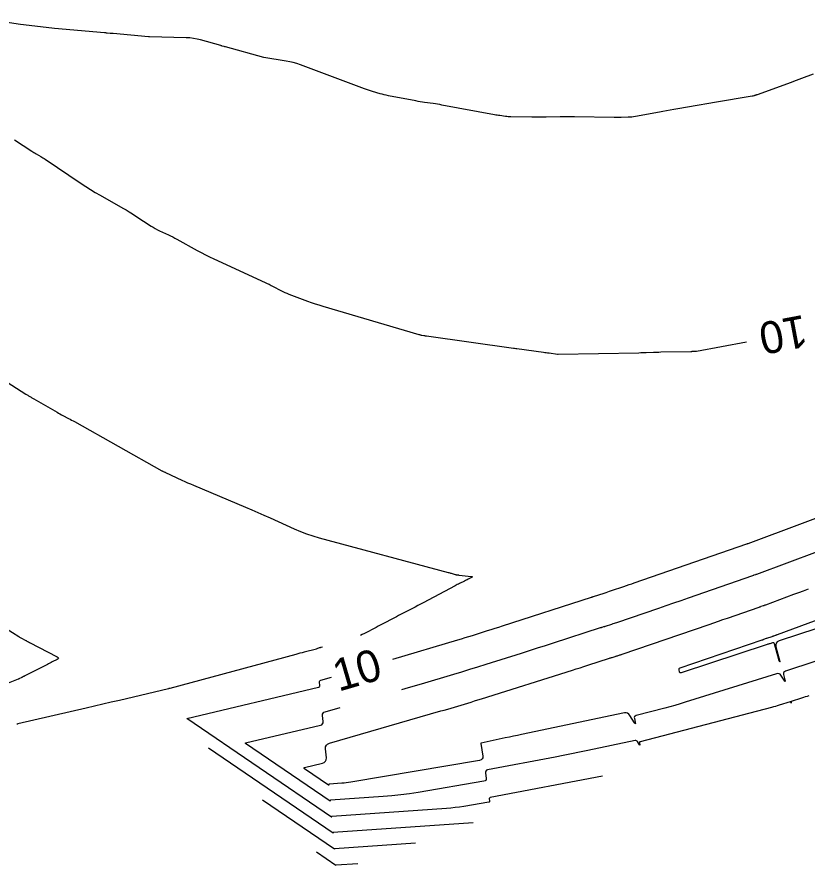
# Model space of a CAD drawing. Extents: x 1797419 to 1809236, y 248759 to 251512.
# Drawn here: x 1797965.5 to 1798113.5, y 248838.1 to 248997 of the extents above; entities that cross this region are included whole.
import ezdxf

# ---------------------------------------------------------------- set-up
doc = ezdxf.new("R2010")
doc.units = 0
doc.layers.add('33', color=7, linetype='Continuous')
doc.layers.add('34', color=7, linetype='Continuous')

msp = doc.modelspace()

# ---------------------------------------------------------------- linework, layer by layer
at = {"layer": '33'}
for points in [[(1797964.99, 248973.98), (1797968.24, 248971.9), (1797968.44, 248971.77), (1797968.65, 248971.64), (1797968.86, 248971.51), (1797969.07, 248971.39), (1797969.92, 248970.9), (1797970.13, 248970.77), (1797970.33, 248970.65), (1797970.54, 248970.51), (1797970.74, 248970.38), (1797977.48, 248965.84), (1797978.36, 248965.26), (1797979.25, 248964.7), (1797980.15, 248964.15), (1797981.06, 248963.63), (1797985.29, 248961.22), (1797985.92, 248960.86), (1797986.53, 248960.48), (1797987.15, 248960.1), (1797987.75, 248959.71), (1797990.61, 248957.84), (1797990.99, 248957.6), (1797991.39, 248957.37), (1797991.79, 248957.16), (1797992.2, 248956.96), (1797993.84, 248956.19), (1797994.25, 248955.99), (1797994.66, 248955.79), (1797995.06, 248955.58), (1797995.46, 248955.36), (1797999.24, 248953.28), (1798000, 248952.87), (1798000.78, 248952.47), (1798001.55, 248952.08), (1798002.34, 248951.71), (1798012, 248947.27), (1798012.37, 248947.1), (1798012.74, 248946.92), (1798013.11, 248946.73), (1798013.47, 248946.54), (1798014.93, 248945.76), (1798015.29, 248945.57), (1798015.67, 248945.4), (1798016.04, 248945.24), (1798016.43, 248945.09), (1798019.9, 248943.79), (1798020.61, 248943.53), (1798021.33, 248943.29), (1798022.05, 248943.05), (1798022.77, 248942.83), (1798040.78, 248937.53), (1798040.89, 248937.5), (1798041.01, 248937.47), (1798041.13, 248937.44), (1798041.25, 248937.41), (1798041.72, 248937.32), (1798041.84, 248937.3), (1798041.96, 248937.28), (1798042.08, 248937.26), (1798042.2, 248937.25), (1798058.5, 248934.98), (1798058.56, 248934.97), (1798058.61, 248934.97), (1798058.67, 248934.96), (1798058.72, 248934.95), (1798058.93, 248934.91), (1798058.99, 248934.9), (1798059.04, 248934.89), (1798059.09, 248934.88), (1798059.15, 248934.87), (1798064.12, 248934.2), (1798064.38, 248934.17), (1798064.65, 248934.13), (1798064.92, 248934.09), (1798065.18, 248934.06), (1798066.76, 248933.84), (1798066.78, 248933.84), (1798066.8, 248933.84), (1798066.83, 248933.83), (1798066.84, 248933.83), (1798066.85, 248933.83), (1798066.86, 248933.83), (1798066.87, 248933.83), (1798082.03, 248934.11), (1798082.38, 248934.12), (1798082.72, 248934.13), (1798083.06, 248934.14), (1798083.4, 248934.15), (1798084.76, 248934.2), (1798085.1, 248934.21), (1798085.45, 248934.22), (1798085.79, 248934.23), (1798086.13, 248934.24), (1798091.77, 248934.36), (1798091.86, 248934.36), (1798091.95, 248934.36), (1798092.03, 248934.37), (1798092.12, 248934.37), (1798092.46, 248934.38), (1798092.55, 248934.39), (1798092.64, 248934.39), (1798092.72, 248934.41), (1798092.81, 248934.42), (1798102.18, 248936.15)], [(1798035.92, 248876.67), (1798048.07, 248880.28), (1798048.77, 248880.49), (1798049.47, 248880.71), (1798050.17, 248880.92), (1798050.87, 248881.14), (1798053.66, 248882.02), (1798054.36, 248882.24), (1798055.06, 248882.47), (1798055.75, 248882.69), (1798056.45, 248882.91), (1798073.17, 248888.3), (1798073.19, 248888.31), (1798073.22, 248888.32), (1798073.25, 248888.33), (1798073.28, 248888.34), (1798073.39, 248888.38), (1798073.42, 248888.38), (1798073.45, 248888.39), (1798073.48, 248888.4), (1798073.5, 248888.41), (1798075.51, 248889.06), (1798075.86, 248889.17), (1798076.2, 248889.29), (1798076.54, 248889.4), (1798076.89, 248889.52), (1798079.18, 248890.3), (1798079.68, 248890.47), (1798080.17, 248890.64), (1798080.67, 248890.81), (1798081.16, 248890.99), (1798102.27, 248898.31), (1798102.3, 248898.32), (1798102.33, 248898.34), (1798102.4, 248898.36), (1798102.42, 248898.37), (1798102.44, 248898.37), (1798102.46, 248898.38), (1798102.47, 248898.38), (1798122.38, 248905.79)], [(1798075.18, 248854.75), (1798054.14, 248850.74), (1798054.06, 248850.71), (1798054.01, 248850.66), (1798053.98, 248850.59), (1798053.98, 248850.5), (1798054.04, 248850.11), (1798054.04, 248850.02), (1798054.01, 248849.95), (1798053.95, 248849.91), (1798053.87, 248849.88), (1798049.21, 248849.09), (1798048.4, 248848.97), (1798047.59, 248848.86), (1798046.77, 248848.77), (1798045.95, 248848.7), (1798024.47, 248847.2), (1798024.46, 248847.2), (1798024.45, 248847.19), (1798024.44, 248847.18), (1798024.44, 248847.16), (1798024.45, 248847.09), (1798024.45, 248847.08), (1798024.44, 248847.07), (1798024.44, 248847.07), (1798024.42, 248847.08), (1797997.3, 248865.54), (1797997.29, 248865.54), (1797997.29, 248865.54), (1797997.29, 248865.55), (1797997.29, 248865.55), (1797997.29, 248865.56), (1797997.29, 248865.56), (1797997.29, 248865.57), (1797997.29, 248865.57), (1797997.3, 248865.57), (1798021.98, 248871.41), (1798022.1, 248871.46), (1798022.19, 248871.54), (1798022.23, 248871.64), (1798022.24, 248871.77), (1798022.19, 248872.36), (1798022.19, 248872.49), (1798022.24, 248872.6), (1798022.32, 248872.68), (1798022.44, 248872.73), (1798024.41, 248873.3)]]:
    msp.add_lwpolyline(points, dxfattribs=at)
at = {"layer": '34'}
for points in [[(1798114.71, 248986.28), (1798112.49, 248985.48), (1798112, 248985.3), (1798111.51, 248985.12), (1798111.02, 248984.94), (1798110.53, 248984.76), (1798104.16, 248982.43), (1798104.13, 248982.42), (1798104.1, 248982.41), (1798104.07, 248982.4), (1798104.04, 248982.39), (1798103.88, 248982.34), (1798103.87, 248982.33), (1798103.85, 248982.33), (1798103.84, 248982.33), (1798103.82, 248982.32), (1798103.77, 248982.31), (1798103.76, 248982.3), (1798103.74, 248982.3), (1798103.73, 248982.29), (1798103.71, 248982.29), (1798103.63, 248982.26), (1798103.61, 248982.26), (1798103.59, 248982.25), (1798103.57, 248982.25), (1798103.55, 248982.24), (1798103.38, 248982.19), (1798103.34, 248982.18), (1798103.31, 248982.17), (1798103.27, 248982.17), (1798103.23, 248982.16), (1798096.21, 248980.99), (1798095.84, 248980.93), (1798095.48, 248980.87), (1798095.12, 248980.8), (1798094.76, 248980.74), (1798093.31, 248980.47), (1798092.95, 248980.4), (1798092.59, 248980.34), (1798092.22, 248980.28), (1798091.86, 248980.22), (1798088.55, 248979.67), (1798087.87, 248979.55), (1798087.2, 248979.44), (1798086.53, 248979.32), (1798085.86, 248979.2), (1798081.36, 248978.37), (1798081.03, 248978.31), (1798080.7, 248978.27), (1798080.37, 248978.24), (1798080.04, 248978.23), (1798078.71, 248978.2), (1798078.37, 248978.2), (1798078.04, 248978.19), (1798077.71, 248978.2), (1798077.38, 248978.2), (1798069.98, 248978.3), (1798069.31, 248978.31), (1798068.64, 248978.31), (1798067.97, 248978.31), (1798067.3, 248978.3), (1798064.63, 248978.25), (1798063.96, 248978.24), (1798063.29, 248978.23), (1798062.62, 248978.23), (1798061.95, 248978.24), (1798058.03, 248978.31), (1798057.78, 248978.32), (1798057.52, 248978.33), (1798057.26, 248978.36), (1798057, 248978.39), (1798055.97, 248978.53), (1798055.72, 248978.56), (1798055.46, 248978.6), (1798055.21, 248978.64), (1798054.95, 248978.69), (1798045.11, 248980.52), (1798044.7, 248980.6), (1798044.29, 248980.67), (1798043.89, 248980.73), (1798043.48, 248980.79), (1798041.85, 248981.01), (1798041.44, 248981.07), (1798041.04, 248981.14), (1798040.63, 248981.21), (1798040.23, 248981.28), (1798035.07, 248982.27), (1798034.69, 248982.35), (1798034.31, 248982.44), (1798033.93, 248982.53), (1798033.56, 248982.64), (1798032.07, 248983.07), (1798031.7, 248983.19), (1798031.33, 248983.31), (1798030.97, 248983.43), (1798030.6, 248983.56), (1798018.6, 248988.04), (1798017.93, 248988.27), (1798017.26, 248988.46), (1798016.58, 248988.62), (1798015.89, 248988.75), (1798011.72, 248989.4), (1798004.55, 248991.4), (1798004.47, 248991.42), (1798004.4, 248991.45), (1798004.32, 248991.47), (1798004.25, 248991.49), (1798003.95, 248991.57), (1798003.88, 248991.59), (1798003.8, 248991.61), (1798003.73, 248991.63), (1798003.65, 248991.66), (1797999.87, 248992.73), (1797999.22, 248992.89), (1797998.55, 248993.01), (1797997.88, 248993.09), (1797997.2, 248993.13), (1797990.31, 248993.3), (1797990.29, 248993.3), (1797990.28, 248993.3), (1797990.26, 248993.3), (1797990.25, 248993.3), (1797990.17, 248993.31), (1797990.14, 248993.31), (1797990.12, 248993.31), (1797983.48, 248993.9), (1797983.35, 248993.91), (1797983.21, 248993.93), (1797983.07, 248993.94), (1797982.94, 248993.95), (1797982.4, 248994), (1797982.26, 248994.01), (1797982.13, 248994.03), (1797981.99, 248994.04), (1797981.86, 248994.05), (1797972.52, 248994.88), (1797970.92, 248995.04), (1797969.32, 248995.21), (1797967.73, 248995.41), (1797966.14, 248995.64), (1797953.4, 248997.52)], [(1797948.71, 248938.13), (1797967.11, 248926.36), (1797967.23, 248926.28), (1797967.36, 248926.2), (1797967.48, 248926.13), (1797967.61, 248926.05), (1797968.12, 248925.76), (1797968.24, 248925.68), (1797968.37, 248925.61), (1797968.5, 248925.54), (1797968.63, 248925.46), (1797972.98, 248922.94), (1797973.25, 248922.78), (1797973.52, 248922.63), (1797973.79, 248922.49), (1797974.06, 248922.34), (1797975.16, 248921.77), (1797975.43, 248921.63), (1797975.71, 248921.48), (1797975.98, 248921.34), (1797976.25, 248921.19), (1797992.65, 248911.98), (1797992.7, 248911.95), (1797992.75, 248911.92), (1797992.81, 248911.89), (1797992.86, 248911.87), (1797993.09, 248911.77), (1797993.14, 248911.75), (1797993.2, 248911.73), (1797993.25, 248911.7), (1797993.31, 248911.68), (1797996.39, 248910.23), (1797996.92, 248909.99), (1797997.45, 248909.75), (1797997.99, 248909.51), (1797998.53, 248909.28), (1798008.33, 248905.17), (1798009.47, 248904.69), (1798010.62, 248904.19), (1798011.76, 248903.69), (1798012.9, 248903.18), (1798017.44, 248901.12), (1798018.58, 248900.63), (1798019.74, 248900.18), (1798020.92, 248899.79), (1798022.12, 248899.44), (1798046.28, 248892.93), (1798046.42, 248892.89), (1798046.57, 248892.85), (1798046.71, 248892.81), (1798046.85, 248892.77), (1798047.59, 248892.55), (1798047.65, 248892.54), (1798047.71, 248892.52), (1798047.77, 248892.51), (1798047.83, 248892.5), (1798048.08, 248892.47), (1798048.14, 248892.46), (1798048.2, 248892.45), (1798048.26, 248892.44), (1798048.32, 248892.44), (1798050.61, 248892.18), (1798050.75, 248892.15), (1798050.8, 248892.11), (1798050.77, 248892.05), (1798050.65, 248891.97), (1798050, 248891.64), (1798049.83, 248891.56), (1798049.67, 248891.48), (1798049.5, 248891.39), (1798049.34, 248891.31), (1798048.41, 248890.85), (1798048.2, 248890.74), (1798047.99, 248890.64), (1798047.79, 248890.53), (1798047.58, 248890.42), (1798041.6, 248887.24), (1798041.1, 248886.98), (1798040.6, 248886.72), (1798040.1, 248886.45), (1798039.6, 248886.19), (1798037.36, 248885.03), (1798036.98, 248884.83), (1798036.6, 248884.63), (1798036.22, 248884.43), (1798035.83, 248884.23), (1798034.31, 248883.43), (1798033.93, 248883.23), (1798033.55, 248883.03), (1798033.17, 248882.83), (1798032.79, 248882.63), (1798030.63, 248881.51), (1798030.14, 248881.27), (1798029.84, 248881.14)], [(1798037.59, 248870.98), (1798038.23, 248871.17), (1798039.74, 248871.61), (1798041.26, 248872.06), (1798047.33, 248873.87), (1798048.84, 248874.32), (1798050.36, 248874.78), (1798051.87, 248875.25), (1798053.38, 248875.72), (1798060.03, 248877.82), (1798061.53, 248878.3), (1798063.03, 248878.77), (1798064.53, 248879.25), (1798066.03, 248879.74), (1798074.85, 248882.58), (1798074.93, 248882.61), (1798075.01, 248882.63), (1798075.08, 248882.65), (1798075.16, 248882.68), (1798075.46, 248882.78), (1798075.54, 248882.8), (1798075.62, 248882.82), (1798075.69, 248882.85), (1798075.77, 248882.87), (1798076.98, 248883.26), (1798077.21, 248883.34), (1798077.43, 248883.41), (1798077.66, 248883.49), (1798077.89, 248883.56), (1798085.77, 248886.26), (1798087.16, 248886.74), (1798088.55, 248887.22), (1798089.93, 248887.7), (1798091.32, 248888.18), (1798103.4, 248892.37), (1798103.47, 248892.39), (1798103.53, 248892.41), (1798103.59, 248892.44), (1798103.65, 248892.46), (1798103.89, 248892.54), (1798103.95, 248892.56), (1798104.01, 248892.58), (1798104.07, 248892.6), (1798104.13, 248892.63), (1798115.47, 248896.84)], [(1798125.6, 248879.73), (1798109.48, 248874.44), (1798109.28, 248874.33), (1798109.15, 248874.19), (1798109.1, 248874.01), (1798109.13, 248873.78), (1798109.4, 248872.79), (1798109.44, 248872.6), (1798109.43, 248872.52), (1798109.37, 248872.56), (1798109.25, 248872.72), (1798108.65, 248873.65), (1798108.49, 248873.84), (1798108.3, 248873.95), (1798108.08, 248873.98), (1798107.84, 248873.94), (1798090.69, 248868.59), (1798089.74, 248868.3), (1798088.78, 248868.02), (1798087.83, 248867.75), (1798086.87, 248867.5), (1798081.49, 248866.09), (1798081.32, 248866.02), (1798081.21, 248865.92), (1798081.16, 248865.77), (1798081.18, 248865.59), (1798081.34, 248864.79), (1798081.37, 248864.63), (1798081.35, 248864.57), (1798081.3, 248864.61), (1798081.21, 248864.73), (1798080.35, 248866.14), (1798080.15, 248866.39), (1798079.91, 248866.55), (1798079.63, 248866.61), (1798079.31, 248866.59), (1798060.03, 248862.56), (1798059.27, 248862.4), (1798058.51, 248862.24), (1798057.75, 248862.08), (1798056.99, 248861.92), (1798052.49, 248860.96), (1798052.46, 248860.95), (1798052.44, 248860.93), (1798052.43, 248860.91), (1798052.43, 248860.87), (1798052.78, 248858.53), (1798052.78, 248858.21), (1798052.68, 248857.97), (1798052.48, 248857.8), (1798052.18, 248857.71), (1798028.01, 248853.62), (1798027.6, 248853.56), (1798027.19, 248853.51), (1798026.78, 248853.46), (1798026.37, 248853.43), (1798023.95, 248853.26), (1798023.93, 248853.25), (1798023.91, 248853.24), (1798023.9, 248853.22), (1798023.9, 248853.2), (1798023.91, 248853.09), (1798023.91, 248853.07), (1798023.9, 248853.06), (1798023.89, 248853.06), (1798023.87, 248853.07), (1798019.34, 248856.15), (1798019.32, 248856.17), (1798019.31, 248856.19), (1798019.3, 248856.21), (1798019.29, 248856.23), (1798019.28, 248856.33), (1798019.28, 248856.35), (1798019.29, 248856.37), (1798019.31, 248856.38), (1798019.33, 248856.39), (1798022.72, 248857.19), (1798023.07, 248857.33), (1798023.31, 248857.54), (1798023.44, 248857.84), (1798023.45, 248858.21), (1798023.31, 248859.87), (1798023.32, 248860.24), (1798023.45, 248860.55), (1798023.69, 248860.77), (1798024.03, 248860.93), (1798044.93, 248866.97), (1798045.56, 248867.15), (1798046.19, 248867.33), (1798046.83, 248867.52), (1798047.46, 248867.71), (1798049.98, 248868.46), (1798050.61, 248868.65), (1798051.24, 248868.84), (1798051.87, 248869.03), (1798052.5, 248869.23), (1798069.56, 248874.62), (1798070.29, 248874.85), (1798071.01, 248875.08), (1798071.73, 248875.31), (1798072.46, 248875.54), (1798076.54, 248876.86), (1798076.66, 248876.9), (1798076.79, 248876.94), (1798076.91, 248876.98), (1798077.04, 248877.02), (1798077.56, 248877.18), (1798077.67, 248877.22), (1798077.78, 248877.25), (1798077.89, 248877.29), (1798078, 248877.32), (1798078.45, 248877.47), (1798078.56, 248877.5), (1798078.67, 248877.54), (1798078.78, 248877.58), (1798078.89, 248877.61), (1798095.21, 248883.2), (1798096.06, 248883.49), (1798096.92, 248883.79), (1798097.77, 248884.08), (1798098.63, 248884.38), (1798104.54, 248886.43), (1798104.65, 248886.47), (1798104.75, 248886.51), (1798104.86, 248886.54), (1798104.96, 248886.58), (1798105.38, 248886.72), (1798105.48, 248886.76), (1798105.59, 248886.79), (1798105.69, 248886.83), (1798105.8, 248886.87), (1798111.07, 248888.83), (1798111.98, 248889.17), (1798112.89, 248889.51), (1798113.81, 248889.84)], [(1798125.65, 248885.81), (1798108.29, 248880.1), (1798107.95, 248879.93), (1798107.74, 248879.7), (1798107.66, 248879.39), (1798107.71, 248879.01), (1798108.46, 248876.25), (1798108.47, 248876.21), (1798108.46, 248876.2), (1798108.45, 248876.2), (1798108.43, 248876.24), (1798108.31, 248876.42), (1798108.28, 248876.46), (1798108.26, 248876.51), (1798108.24, 248876.56), (1798108.22, 248876.61), (1798107.43, 248879.53), (1798107.38, 248879.65), (1798107.31, 248879.72), (1798107.21, 248879.74), (1798107.09, 248879.73), (1798106.56, 248879.58), (1798106.43, 248879.55), (1798106.29, 248879.51), (1798106.16, 248879.47), (1798106.03, 248879.43), (1798089.93, 248874.12), (1798089.83, 248874.1), (1798089.75, 248874.12), (1798089.69, 248874.18), (1798089.66, 248874.27), (1798089.56, 248874.73), (1798089.56, 248874.83), (1798089.58, 248874.92), (1798089.64, 248874.99), (1798089.74, 248875.03), (1798105.14, 248880.31), (1798105.22, 248880.33), (1798105.29, 248880.36), (1798105.37, 248880.38), (1798105.44, 248880.41), (1798105.96, 248880.59), (1798106, 248880.6), (1798106.99, 248880.94), (1798107.08, 248880.97), (1798107.16, 248881), (1798107.25, 248881.04), (1798107.34, 248881.07), (1798107.68, 248881.19), (1798107.76, 248881.23), (1798107.85, 248881.26), (1798107.93, 248881.29), (1798108.02, 248881.32), (1798132.7, 248890.42)], [(1797963.48, 248882.4), (1797965.8, 248880.91), (1797965.93, 248880.83), (1797966.07, 248880.75), (1797966.2, 248880.67), (1797966.34, 248880.6), (1797967.04, 248880.23), (1797967.11, 248880.19), (1797967.18, 248880.16), (1797967.24, 248880.12), (1797967.31, 248880.08), (1797967.57, 248879.93), (1797967.63, 248879.9), (1797967.7, 248879.86), (1797967.76, 248879.82), (1797967.83, 248879.79), (1797973, 248877.11), (1797973.17, 248877), (1797973.23, 248876.88), (1797973.17, 248876.76), (1797973, 248876.64), (1797972.09, 248876.17), (1797971.86, 248876.05), (1797971.64, 248875.93), (1797971.41, 248875.81), (1797971.18, 248875.7), (1797966.95, 248873.55), (1797966.89, 248873.52), (1797966.83, 248873.49), (1797966.77, 248873.46), (1797966.71, 248873.43), (1797966.48, 248873.31), (1797966.42, 248873.28), (1797966.36, 248873.25), (1797966.3, 248873.22), (1797966.24, 248873.19), (1797965.97, 248873.06), (1797965.91, 248873.02), (1797965.84, 248872.99), (1797965.78, 248872.96), (1797965.71, 248872.94), (1797963.52, 248872.07)], [(1798022.75, 248878.95), (1798022.46, 248878.87), (1798022.38, 248878.84), (1798022.3, 248878.82), (1798022.21, 248878.79), (1798022.13, 248878.77), (1798021.65, 248878.63), (1798021.64, 248878.63), (1798021.63, 248878.62), (1798021.63, 248878.61), (1798021.63, 248878.6), (1798021.63, 248878.55), (1798021.63, 248878.54), (1798021.63, 248878.53), (1798021.62, 248878.53), (1798021.61, 248878.52), (1798019.28, 248877.97), (1798018.89, 248877.88), (1798018.5, 248877.78), (1798018.11, 248877.68), (1798017.72, 248877.57), (1797994.11, 248871.19), (1797994.05, 248871.18), (1797993.99, 248871.16), (1797993.93, 248871.15), (1797993.87, 248871.13), (1797984.66, 248868.95), (1797983.1, 248868.59), (1797981.55, 248868.22), (1797979.99, 248867.86), (1797978.43, 248867.5), (1797965.61, 248864.53), (1797965.6, 248864.52), (1797965.43, 248864.5)], [(1798113.87, 248869.82), (1798113.53, 248869.71), (1798113.2, 248869.6), (1798112.86, 248869.49), (1798112.52, 248869.38), (1798110.58, 248868.74), (1798110.55, 248868.72), (1798110.53, 248868.7), (1798110.52, 248868.68), (1798110.53, 248868.64), (1798110.57, 248868.5), (1798110.57, 248868.47), (1798110.57, 248868.46), (1798110.56, 248868.47), (1798110.55, 248868.49), (1798110.46, 248868.62), (1798110.44, 248868.65), (1798110.41, 248868.67), (1798110.38, 248868.67), (1798110.34, 248868.67), (1798108.31, 248868.03), (1798107.95, 248867.92), (1798107.6, 248867.82), (1798107.25, 248867.72), (1798106.89, 248867.63), (1798082.28, 248861.2), (1798082.2, 248861.17), (1798082.16, 248861.13), (1798082.14, 248861.06), (1798082.14, 248860.99), (1798082.21, 248860.64), (1798082.22, 248860.58), (1798082.22, 248860.55), (1798082.2, 248860.56), (1798082.16, 248860.62), (1798081.79, 248861.22), (1798081.7, 248861.33), (1798081.6, 248861.4), (1798081.48, 248861.42), (1798081.34, 248861.41), (1798072.44, 248859.55), (1798070.91, 248859.24), (1798069.38, 248858.93), (1798067.84, 248858.62), (1798066.31, 248858.33), (1798053.67, 248855.92), (1798053.46, 248855.85), (1798053.32, 248855.72), (1798053.26, 248855.55), (1798053.26, 248855.33), (1798053.4, 248854.36), (1798053.4, 248854.14), (1798053.34, 248853.97), (1798053.2, 248853.85), (1798052.99, 248853.79), (1798040.66, 248851.7), (1798039.03, 248851.45), (1798037.38, 248851.23), (1798035.74, 248851.06), (1798034.09, 248850.92), (1798024.21, 248850.23), (1798024.19, 248850.22), (1798024.18, 248850.22), (1798024.17, 248850.2), (1798024.17, 248850.18), (1798024.18, 248850.09), (1798024.18, 248850.07), (1798024.17, 248850.07), (1798024.16, 248850.06), (1798024.15, 248850.07), (1798008.32, 248860.85), (1798008.31, 248860.85), (1798008.3, 248860.86), (1798008.29, 248860.88), (1798008.29, 248860.89), (1798008.29, 248860.95), (1798008.29, 248860.96), (1798008.29, 248860.97), (1798008.3, 248860.98), (1798008.31, 248860.98), (1798022.35, 248864.3), (1798022.59, 248864.39), (1798022.75, 248864.54), (1798022.83, 248864.74), (1798022.85, 248864.99), (1798022.75, 248866.11), (1798022.76, 248866.37), (1798022.84, 248866.57), (1798023, 248866.72), (1798023.24, 248866.83), (1798026.06, 248867.64)], [(1798050.94, 248846.01), (1798024.73, 248844.17), (1798024.72, 248844.17), (1798024.72, 248844.16), (1798024.71, 248844.16), (1798024.71, 248844.14), (1798024.72, 248844.1), (1798024.72, 248844.09), (1798024.71, 248844.08), (1798024.71, 248844.08), (1798024.7, 248844.09), (1798001.34, 248859.98)], [(1798040.14, 248842.2), (1798024.99, 248841.14), (1798024.99, 248841.14), (1798024.98, 248841.14), (1798024.98, 248841.13), (1798024.98, 248841.13), (1798024.98, 248841.1), (1798024.98, 248841.09), (1798024.98, 248841.09), (1798024.98, 248841.09), (1798024.97, 248841.09), (1798011.48, 248850.28)], [(1798021.61, 248840.57), (1798025.25, 248838.1), (1798025.25, 248838.1), (1798025.25, 248838.1), (1798025.25, 248838.11), (1798025.25, 248838.11), (1798025.26, 248838.11), (1798029.34, 248838.4)]]:
    msp.add_lwpolyline(points, dxfattribs=at)

# ---------------------------------------------------------------- texts
at = {"layer": '33'}
for rotation, p in [(190.6994, (1798112.92, 248941.23)), (16.3355, (1798025.73, 248870.56))]:
    msp.add_text('10', height=6, rotation=rotation, dxfattribs=at).set_placement(p)

doc.saveas('drawing.dxf')
